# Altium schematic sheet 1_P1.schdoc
size 307 x 218 mm; Symbol: Drawing-Symbol_A4; Device: Drawing-Symbol_A4; Company: 嘉立创EDA; Version: V1.0; Page Size: A4; @Project Name: 基于LVGL与Free RTOS的智能终端; @Page Count: 1; @Update Date: 2025-12-01; @Create Date: 2025-12-01; @Schematic Name: Schematic1; @Page No: 1; @Page Name: P1; @Board Name: Board1; @Create Time: 09:17:02; @Update Time: 23:02:25; Title Block Position: 3; Size: A4; Width: 1170; Height: 825; Region Start: 1; X Region Count: 6; Y Region Count: 4; Blade Width: 10
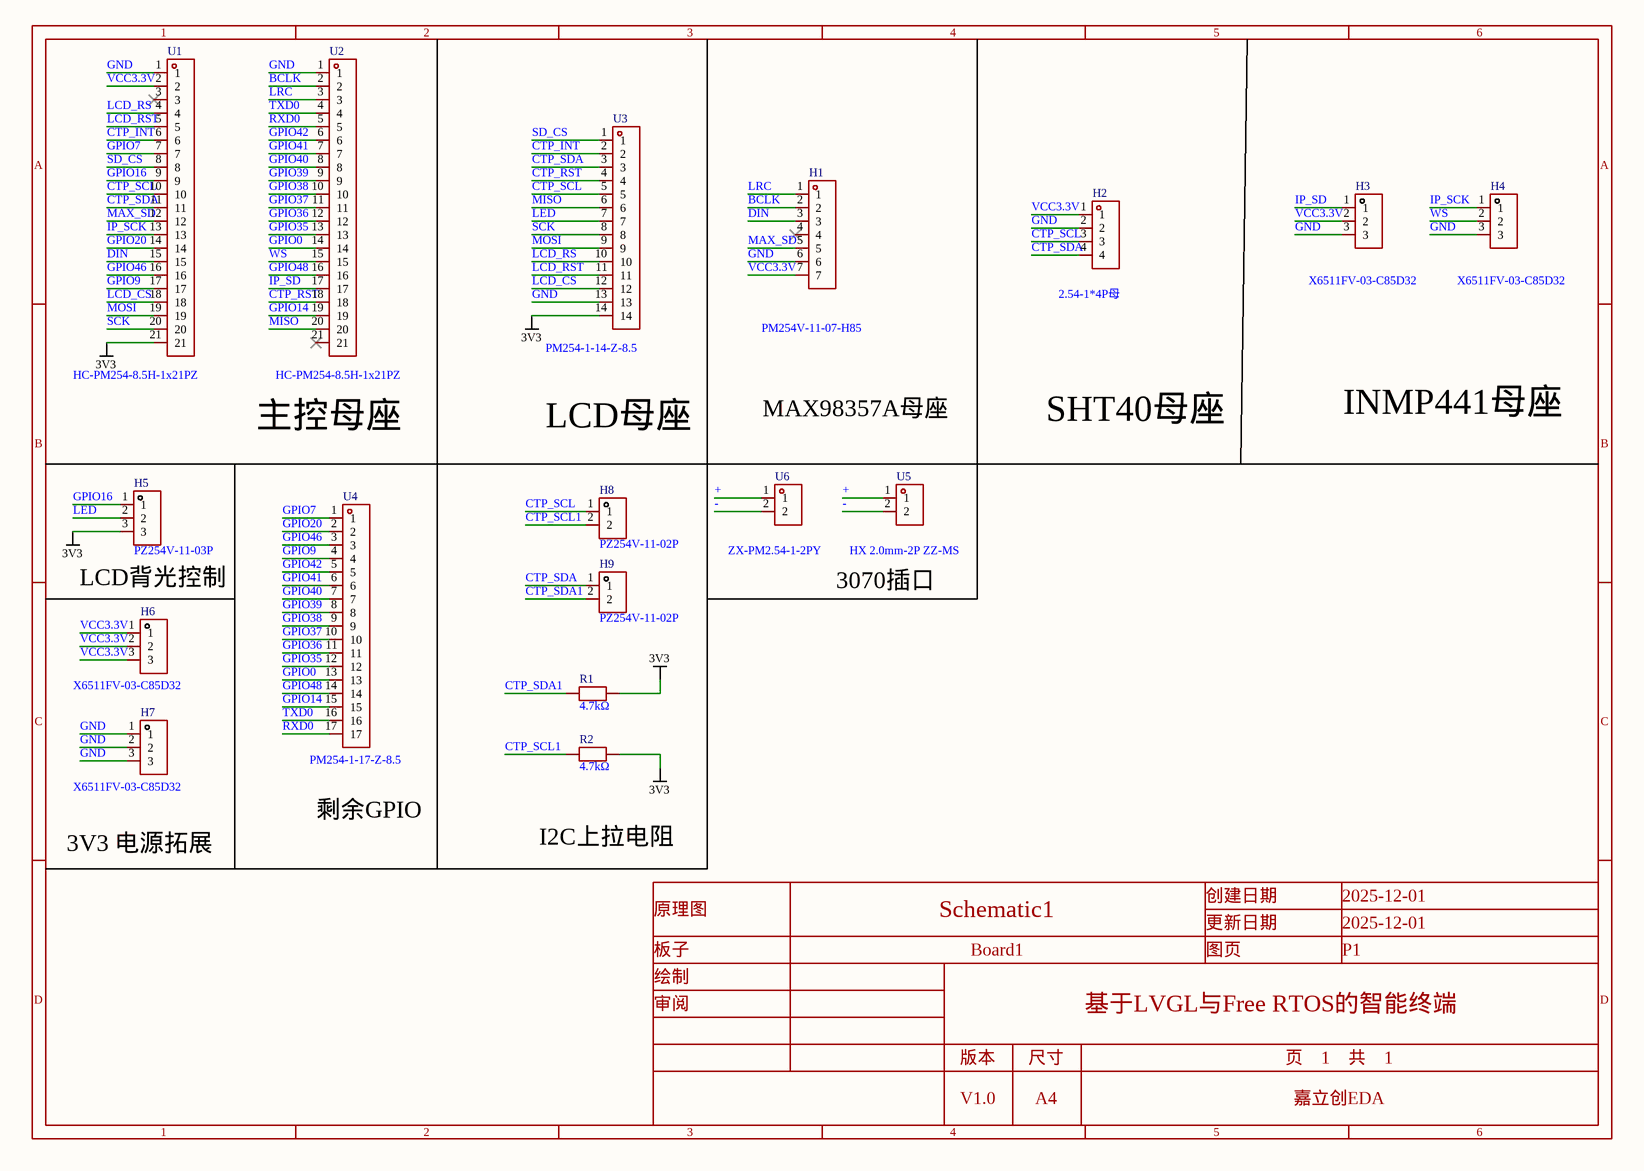
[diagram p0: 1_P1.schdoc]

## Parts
H1  PM254V-11-07-H85  [HDR-TH_7P-P2.54-V-F]
H2  2.54-1*4P母  [HDR-TH_4P-P2.54-V-F]
H3  X6511FV-03-C85D32  [HDR-TH_3P-P2.54-V-F]
H4  X6511FV-03-C85D32  [HDR-TH_3P-P2.54-V-F]
H5  PZ254V-11-03P  [HDR-TH_3P-P2.54-V-M]
H6  X6511FV-03-C85D32  [HDR-TH_3P-P2.54-V-F]
H7  X6511FV-03-C85D32  [HDR-TH_3P-P2.54-V-F]
H8  PZ254V-11-02P  [HDR-TH_2P-P2.54-V-M]
H9  PZ254V-11-02P  [HDR-TH_2P-P2.54-V-M]
R1  4.7kΩ  [R0603]
R2  4.7kΩ  [R0603]
U1  HC-PM254-8.5H-1x21PZ  [HDR-TH_21P-P2.54-V-F_1]
U2  HC-PM254-8.5H-1x21PZ  [HDR-TH_21P-P2.54-V-F_1]
U3  PM254-1-14-Z-8.5  [HDR-TH_14P-P2.54-V-F-1]
U4  PM254-1-17-Z-8.5  [HDR-TH_17P-P2.54-V-F]
U5  HX 2.0mm-2P ZZ-MS  [CONN-TH_2P-P2.00_HX-2.0MM-2P-ZZ]
U6  ZX-PM2.54-1-2PY  [HDR-TH_2P-P2.54-V-F]

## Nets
3V3: H5.3 R1.2 R2.2 U1.21 U3.14
+: U5.1 U6.1
-: U5.2 U6.2
BCLK: H1.2 U2.2
CTP_INT: U1.6 U3.2
CTP_RST: U2.18 U3.4
CTP_SCL: H2.3 H8.1 U1.10 U3.5
CTP_SCL1: H8.2 R2.1
CTP_SDA: H2.4 H9.1 U1.11 U3.3
CTP_SDA1: H9.2 R1.1
DIN: H1.3 U1.15
GND: H1.6 H2.2 H3.3 H4.3 H7.1 H7.2 H7.3 U1.1 U2.1 U3.13
GPIO0: U2.14 U4.13
GPIO7: U1.7 U4.1
GPIO9: U1.17 U4.4
GPIO14: U2.19 U4.15
GPIO16: H5.1 U1.9
GPIO20: U1.14 U4.2
GPIO35: U2.13 U4.12
GPIO36: U2.12 U4.11
GPIO37: U2.11 U4.10
GPIO38: U2.10 U4.9
GPIO39: U2.9 U4.8
GPIO40: U2.8 U4.7
GPIO41: U2.7 U4.6
GPIO42: U2.6 U4.5
GPIO46: U1.16 U4.3
GPIO48: U2.16 U4.14
IP_SCK: H4.1 U1.13
IP_SD: H3.1 U2.17
LCD_CS: U1.18 U3.12
LCD_RS: U1.4 U3.10
LCD_RST: U1.5 U3.11
LED: H5.2 U3.7
LRC: H1.1 U2.3
MAX_SD: H1.5 U1.12
MISO: U2.20 U3.6
MOSI: U1.19 U3.9
RXD0: U2.5 U4.17
SCK: U1.20 U3.8
SD_CS: U1.8 U3.1
TXD0: U2.4 U4.16
VCC3.3V: H1.7 H2.1 H3.2 H6.1 H6.2 H6.3 U1.2
WS: H4.2 U2.15

Not connected (* = marked no-connect by the designer): H1 4*; U1 3*; U2 21*

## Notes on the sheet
- 主控母座
- LCD母座
- MAX98357A母座
- SHT40母座
- INMP441母座
- 3070插口
- LCD背光控制
- 剩余GPIO
- 3V3 电源拓展
- I2C上拉电阻

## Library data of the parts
H1 = PM254V-11-07-H85: Manufacturer: XFCN(兴飞); Add into BOM: yes; Holes Structure: 1x7P; Pitch: 2.54mm; Circular Hole / Square Hole: 方孔; Number of Positions: 7P; Current Rating: 3A; Voltage Rating (Max): 250V; Holes Direction: 顶部
H2 = 2.54-1*4P母: Manufacturer: BOOMELE(博穆精密); Add into BOM: yes; Holes Structure: 1x4P; Pitch: 2.54mm; Circular Hole / Square Hole: 方孔; Number of Positions: 4P; Current Rating: 3A; Holes Direction: 顶部
H3 H4 H6 H7 = X6511FV-03-C85D32: Manufacturer: XKB Connection(中国星坤); Add into BOM: yes; Holes Structure: 1x3P; Pitch: 2.54mm; Circular Hole / Square Hole: 方孔; Number of Positions: 3P; Current Rating: 3A; Voltage Rating (Max): 250V; Holes Direction: 顶部
H5 = PZ254V-11-03P: Manufacturer: XFCN(兴飞); Symbol: PZ254V-11-03P_C2937625; Add into BOM: yes; Pin Structure: 1x3P; Pitch: 2.54mm; Circluar Pins/Square Pins: 方针; Current Rating: 3A; Voltage Rating (Max): 250V
H8 H9 = PZ254V-11-02P: Manufacturer: XFCN(兴飞); Add into BOM: yes; Pin Structure: 1x2P; Pitch: 2.54mm; Circluar Pins/Square Pins: 方针
R1 R2 = RCA034K7JLF: Manufacturer: HKR(香港电阻); Add into BOM: yes; Tolerance: ±5%; Power(Watts): 100mW; Voltage-Supply(Max): 75V; Temperature Coefficient: ±100ppm/℃
U1 U2 = HC-PM254-8.5H-1x21PZ: Manufacturer: HC(虹成电子); Add into BOM: yes; Holes Structure: 1x21P; Pitch: 2.54mm; Circular Hole / Square Hole: 方孔; Number of Positions: 21P; Current Rating: 3A; Holes Direction: 顶部; PIN Length: 3mm
U3 = PM254-1-14-Z-8.5: Manufacturer: HCTL(华灿天禄); Add into BOM: yes; Holes Structure: 1x14P; Pitch: 2.54mm; Circular Hole / Square Hole: 方孔; Number of Positions: 14P; Current Rating: 3A; Holes Direction: 顶部
U4 = PM254-1-17-Z-8.5: Manufacturer: HCTL(华灿天禄); Add into BOM: yes; Holes Structure: 1x17P; Pitch: 2.54mm; Circular Hole / Square Hole: 方孔; Number of Positions: 17P; Current Rating: 3A; Holes Direction: 顶部
U5 = HX 2.0mm-2P ZZ-MS: Manufacturer: hanxia(韩下); Add into BOM: yes; Pins Structure: 1x2P; Pitch: 2mm; Reference Series: PH; Number of PINs Per Row: 2; Current Rating: 2A; Voltage Rating: 250V; Plastic Material: PA6T; Flame Retardant Rating: UL94V-0
U6 = ZX-PM2.54-1-2PY: Manufacturer: Megastar(兆星); Add into BOM: yes; Holes Structure: 1x2P; Pitch: 2.54mm; Circular Hole / Square Hole: 方孔; Number of Positions: 2P; Current Rating: 3A; Holes Direction: 顶部; PIN Length: 3.2mm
